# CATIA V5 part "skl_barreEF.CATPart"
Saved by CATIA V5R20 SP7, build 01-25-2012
Part number: skl_barreEF
Publications: "Axe pivot EF/Bati", "Axe pivot EF/FG", "Plan EF"
Bounding box of the stored display mesh (mm): x 0 to 0, y -20 to -9.973, z 10 to 89.369
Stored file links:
  U:\IAO_bon\skl_barreEF.CATPart
  U:\IAO_bon\skl_IAO.CATProduct
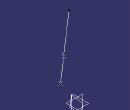
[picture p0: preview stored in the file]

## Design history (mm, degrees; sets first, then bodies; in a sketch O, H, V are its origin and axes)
Set1
  Point1 "Point E": linked copy from another document
  Point2 "Point F": linked copy from another document
  Plane1 "Plan Ref": linked copy from another document
Set2
  Line1: type PtPt, FirstPoint Point1, SecondPoint Point2
  Line2 "Axe pivot EF/Bati": type Normal, RefPoint Point1, RefSkin Plane1, Start 0, End 20
  Line3 "Axe pivot EF/FG": type Normal, RefPoint Point2, RefSkin Plane1, Start 0, End 20
  Plane2 "Plan EF": type Normal, Curve Line3, RefPoint Point2
  Line4: type PtDir, RefPoint Point1, Direction Line1, Start 0, End 80
Body1 (main body)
